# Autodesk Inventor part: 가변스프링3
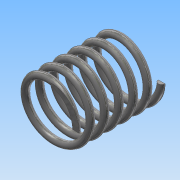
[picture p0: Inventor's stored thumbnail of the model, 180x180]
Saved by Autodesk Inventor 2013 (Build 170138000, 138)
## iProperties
Created: 2019-07
Part Number: 가변스프링3
Material: 강철, 탄소
Document SubType Name: Modeling
Designer: Administrator
Density: 7.87 g/cm^3
Mass: 7.78998 g
Surface Area: 20.0702 cm^2
Volume: 0.989832 cm^3
Author: Administrator
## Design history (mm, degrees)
sketch "스케치1"
  geometry: L1 (0, 0)-(0, 25.33); L2 (0, 25.33)-(16.881, 25.33); C1 r 1 at (8.5, 0)
  constraints: 4 end point, 1 centre point, 1 horizontal alignment, 1 perpendicular, 1 vertical
  dimensions: "d0" = 25.33013 distance of L1.start L1.end (derived); "d1" = 2 diameter of C1; "d2" = 17 diameter of C1.centre L1
feature "코일1" sketch "스케치1" pitch "d3" = 10; turns "d5" = 6; dims "d4" = 25.33013 (= d0), "d6" = 0, angle "d7" = 90 deg, angle "d8" = 90 deg, "d9" = 0, "d10" = 0
sketch "스케치2"
  geometry: L1 (0, 12.5)-(25.33, 12.5); L2 (25.33, 12.5)-(25.33, -12.5); L3 (25.33, -12.5)-(0, -12.5); L4 (0, -12.5)-(0, 12.5); 2 further points
  constraints: 8 end point, 2 parallel, 1 coincident, 1 horizontal, 1 midpoint, 1 perpendicular
  dimensions: "d11" = 25.33013 distance between parallel lines of L2 L4 (derived); "d13" = 25 distance between parallel lines of L1 L3
extrude "돌출1" sketch "스케치2" stored distance "d14" = 50; taper "d15" = 0 deg
node "솔리드1"
